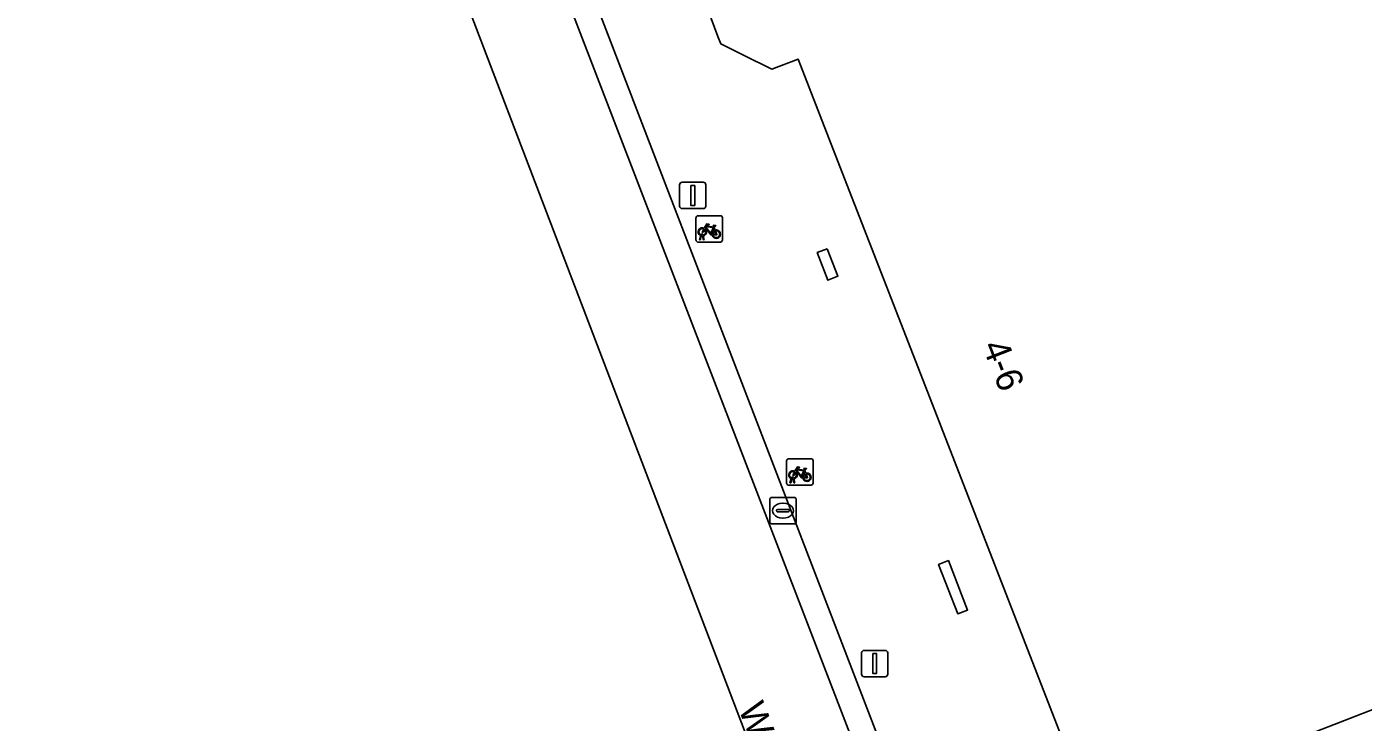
# Model space of a CAD drawing. Extents: x 160856 to 161310, y 384024 to 384878.
# Drawn here: x 160875.2 to 160925.8, y 384720.3 to 384746.6 of the extents above; entities that cross this region are included whole.
import ezdxf

# ---------------------------------------------------------------- set-up
doc = ezdxf.new("R2010")
doc.units = 0
for name, color, linetype in [('IMGEO_Fietsenrek', 7, 'Continuous'), ('IMGEO_Fietspad_gesloten', 7, 'Continuous'), ('IMGEO_Fietspad_open', 7, 'Continuous'), ('IMGEO_Kolk', 7, 'Continuous'), ('IMGEO_Lichtmast', 7, 'Continuous'), ('IMGEO_Openbare_ruimte_label', 7, 'Continuous'), ('IMGEO_Pand', 7, 'Continuous'), ('IMGEO_Pand_nummerreeks', 7, 'Continuous'), ('IMGEO_Voetpad_open', 7, 'Continuous')]:
    doc.layers.add(name, color=color, linetype=linetype)

msp = doc.modelspace()

# ---------------------------------------------------------------- linework, layer by layer
at = {"layer": 'IMGEO_Fietsenrek'}
for p, q in [((160900.511, 384738.519), (160900.511, 384739.36)), ((160900.511, 384739.36), (160900.511, 384738.519)), ((160900.586, 384739.444), (160901.427, 384739.444)), ((160901.427, 384739.444), (160900.586, 384739.444)), ((160901.511, 384739.369), (160901.511, 384738.528)), ((160901.511, 384738.528), (160901.511, 384739.369)), ((160900.638, 384738.528), (160900.677, 384738.688)), ((160900.672, 384738.528), (160900.638, 384738.528)), ((160900.707, 384738.676), (160900.672, 384738.528)), ((160900.749, 384738.7), (160900.748, 384738.704)), ((160900.79, 384738.528), (160900.756, 384738.67)), ((160900.78, 384738.711), (160900.781, 384738.704)), ((160900.788, 384738.674), (160900.823, 384738.528)), ((160900.823, 384738.528), (160900.79, 384738.528)), ((160901.198, 384738.993), (160901.234, 384738.898)), ((160901.436, 384738.444), (160900.595, 384738.444)), ((160900.595, 384738.444), (160901.436, 384738.444)), ((160903.939, 384729.325), (160903.939, 384730.166)), ((160903.939, 384730.166), (160903.939, 384729.325)), ((160904.014, 384730.25), (160904.855, 384730.25)), ((160904.855, 384730.25), (160904.014, 384730.25)), ((160904.939, 384730.175), (160904.939, 384729.334)), ((160904.939, 384729.334), (160904.939, 384730.175)), ((160904.066, 384729.334), (160904.105, 384729.494)), ((160904.135, 384729.482), (160904.1, 384729.334)), ((160904.177, 384729.506), (160904.176, 384729.51)), ((160904.218, 384729.334), (160904.184, 384729.476)), ((160904.208, 384729.517), (160904.209, 384729.51)), ((160904.216, 384729.48), (160904.251, 384729.334)), ((160904.626, 384729.799), (160904.662, 384729.704)), ((160904.864, 384729.25), (160904.023, 384729.25)), ((160904.023, 384729.25), (160904.864, 384729.25)), ((160904.1, 384729.334), (160904.066, 384729.334)), ((160904.251, 384729.334), (160904.218, 384729.334))]:
    msp.add_line(p, q, dxfattribs=at)
for points in [[(160900.824, 384738.97), (160900.919, 384739.134), (160901.005, 384739.12), (160901.007, 384739.111), (160900.951, 384739.1), (160900.924, 384739.055), (160901.18, 384739.014)], [(160901.167, 384738.989), (160900.91, 384739.03), (160900.893, 384739.001), (160901.06, 384738.781), (160901.167, 384738.989)], [(160901.18, 384739.014), (160901.205, 384739.063), (160901.199, 384739.067), (160901.176, 384739.071), (160901.164, 384739.078), (160901.163, 384739.081), (160901.165, 384739.086), (160901.26, 384739.071), (160901.262, 384739.061), (160901.252, 384739.048), (160901.24, 384739.042), (160901.226, 384739.048), (160901.198, 384738.993)], [(160900.845, 384738.918), (160900.793, 384738.828), (160900.753, 384738.803), (160900.754, 384738.85), (160900.809, 384738.944)], [(160901.12, 384738.726), (160901.07, 384738.726), (160900.879, 384738.977), (160900.86, 384738.945)], [(160901.215, 384738.891), (160901.185, 384738.968), (160901.076, 384738.75), (160901.119, 384738.75)], [(160901.149, 384738.75), (160901.269, 384738.749), (160901.225, 384738.863)], [(160901.245, 384738.87), (160901.3, 384738.725), (160901.15, 384738.725)], [(160904.252, 384729.776), (160904.347, 384729.94), (160904.433, 384729.926), (160904.435, 384729.917), (160904.379, 384729.906), (160904.352, 384729.861), (160904.608, 384729.82)], [(160904.273, 384729.724), (160904.221, 384729.634), (160904.181, 384729.609), (160904.182, 384729.656), (160904.237, 384729.75)], [(160904.548, 384729.532), (160904.498, 384729.532), (160904.307, 384729.783), (160904.288, 384729.751)], [(160904.595, 384729.795), (160904.338, 384729.836), (160904.321, 384729.807), (160904.488, 384729.587), (160904.595, 384729.795)], [(160904.643, 384729.697), (160904.613, 384729.774), (160904.504, 384729.556), (160904.547, 384729.556)], [(160904.577, 384729.556), (160904.697, 384729.555), (160904.653, 384729.669)], [(160904.673, 384729.676), (160904.728, 384729.531), (160904.578, 384729.531)], [(160904.608, 384729.82), (160904.633, 384729.869), (160904.627, 384729.873), (160904.604, 384729.877), (160904.592, 384729.884), (160904.591, 384729.887), (160904.593, 384729.892), (160904.688, 384729.877), (160904.69, 384729.867), (160904.68, 384729.854), (160904.668, 384729.848), (160904.654, 384729.854), (160904.626, 384729.799)]]:
    msp.add_lwpolyline(points, dxfattribs=at)
for centre, radius, start, end in [((160900.589, 384739.366), 0.0779, 92.4484, 184.2845), ((160900.589, 384739.366), 0.0779, 92.4484, 184.2845), ((160901.433, 384739.366), 0.0779, 2.4484, 94.2845), ((160901.433, 384739.366), 0.0779, 2.4484, 94.2845), ((160900.589, 384738.522), 0.0779, 182.4484, 274.2845), ((160900.589, 384738.522), 0.0779, 182.4484, 274.2845), ((160900.751, 384738.829), 0.159, 62.6766, 242.1369), ((160900.751, 384738.829), 0.129, 63.3192, 238.903), ((160900.731, 384738.7), 0.0499, 12.8025, 158.6934), ((160900.751, 384738.829), 0.159, 253.9967, 271.7867), ((160900.731, 384738.7), 0.0174, 12.8025, 163.4502), ((160900.751, 384738.829), 0.129, 253.415, 269.0204), ((160900.751, 384738.829), 0.129, 283.6043, 43.4302), ((160900.751, 384738.829), 0.159, 283.5766, 46.6042), ((160901.278, 384738.745), 0.159, 113.3408, 178.3217), ((160901.278, 384738.745), 0.159, 187.0065, 105.7708), ((160901.278, 384738.745), 0.129, 113.923, 177.9556), ((160901.278, 384738.745), 0.129, 188.6715, 104.5883), ((160901.433, 384738.522), 0.0779, 272.4484, 4.2845), ((160901.433, 384738.522), 0.0779, 272.4484, 4.2845), ((160904.017, 384730.172), 0.0779, 92.4484, 184.2845), ((160904.017, 384730.172), 0.0779, 92.4484, 184.2845), ((160904.861, 384730.172), 0.0779, 2.4484, 94.2845), ((160904.861, 384730.172), 0.0779, 2.4484, 94.2845), ((160904.179, 384729.635), 0.159, 62.6766, 242.1369), ((160904.179, 384729.635), 0.129, 63.3192, 238.903), ((160904.159, 384729.506), 0.0499, 12.8025, 158.6934), ((160904.179, 384729.635), 0.159, 253.9967, 271.7867), ((160904.159, 384729.506), 0.0174, 12.8025, 163.4502), ((160904.179, 384729.635), 0.129, 253.415, 269.0204), ((160904.179, 384729.635), 0.129, 283.6043, 43.4302), ((160904.179, 384729.635), 0.159, 283.5766, 46.6042), ((160904.706, 384729.551), 0.159, 113.3408, 178.3217), ((160904.706, 384729.551), 0.159, 187.0065, 105.7708), ((160904.706, 384729.551), 0.129, 113.923, 177.9556), ((160904.706, 384729.551), 0.129, 188.6715, 104.5883), ((160904.017, 384729.328), 0.0779, 182.4484, 274.2845), ((160904.017, 384729.328), 0.0779, 182.4484, 274.2845), ((160904.861, 384729.328), 0.0779, 272.4484, 4.2845), ((160904.861, 384729.328), 0.0779, 272.4484, 4.2845)]:
    msp.add_arc(centre, radius, start, end, dxfattribs=at)
at = {"layer": 'IMGEO_Fietspad_gesloten'}
msp.add_lwpolyline([(160952.428, 384599.868), (160937.604, 384638.593), (160892.484, 384755.839), (160890.883, 384755.238), (160892.527, 384749.494), (160889.824, 384754.841), (160889.132, 384754.582), (160951.015, 384592.51), (160969.346, 384573.161), (160977.866, 384562.895)], dxfattribs=at)
at = {"layer": 'IMGEO_Fietspad_open'}
msp.add_lwpolyline([(160921.747, 384682.423), (160893.385, 384756.183), (160892.484, 384755.839), (160937.604, 384638.593), (160952.428, 384599.868)], dxfattribs=at)
at = {"layer": 'IMGEO_Kolk'}
for p, q in [((160903.301, 384727.86), (160903.301, 384728.712)), ((160903.376, 384728.786), (160904.228, 384728.786)), ((160903.789, 384728.566), (160903.814, 384728.566)), ((160904.302, 384728.712), (160904.302, 384727.86)), ((160903.56, 384728.28), (160903.56, 384728.292)), ((160903.998, 384728.243), (160903.6, 384728.243)), ((160903.603, 384728.329), (160904.001, 384728.329)), ((160903.812, 384728.006), (160903.787, 384728.006)), ((160904.044, 384728.292), (160904.044, 384728.28)), ((160904.228, 384727.786), (160903.376, 384727.786))]:
    msp.add_line(p, q, dxfattribs=at)
for points in [[(160903.301, 384727.86), (160903.301, 384728.712)], [(160903.376, 384728.786), (160904.228, 384728.786)], [(160904.302, 384728.712), (160904.302, 384727.86)], [(160904.228, 384727.786), (160903.376, 384727.786)]]:
    msp.add_lwpolyline(points, dxfattribs=at)
for centre, radius, start, end in [((160903.378, 384728.71), 0.0765, 91.552, 178.448), ((160903.378, 384728.71), 0.0765, 91.552, 178.448), ((160904.226, 384728.71), 0.0765, 1.552, 88.448), ((160904.226, 384728.71), 0.0765, 1.552, 88.448), ((160903.6, 384728.289), 0.0403, 85.8775, 175.7526), ((160903.597, 384728.279), 0.0366, 178.938, 274.7102), ((160904.001, 384728.286), 0.043, 264.8664, 352.4533), ((160904.005, 384728.291), 0.0386, 1.7309, 96.639), ((160903.378, 384727.862), 0.0765, 181.552, 268.448), ((160903.378, 384727.862), 0.0765, 181.552, 268.448), ((160904.226, 384727.862), 0.0765, 271.552, 358.448), ((160904.226, 384727.862), 0.0765, 271.552, 358.448)]:
    msp.add_arc(centre, radius, start, end, dxfattribs=at)
for centre, major_axis, ratio, start_param, end_param in [((160903.788, 384728.286), (-0.387, 0.002), 0.722429, 4.712389, 7.853982), ((160903.813, 384728.286), (-0.39, 0.002), 0.717154, 1.570796, 4.712389)]:
    msp.add_ellipse(centre, major_axis=major_axis, ratio=ratio, start_param=start_param, end_param=end_param, dxfattribs=at)
at = {"layer": 'IMGEO_Lichtmast'}
for p, q in [((160899.891, 384739.811), (160899.891, 384740.611)), ((160899.891, 384740.611), (160899.891, 384739.811)), ((160899.991, 384740.711), (160900.781, 384740.711)), ((160900.781, 384740.711), (160899.991, 384740.711)), ((160900.881, 384740.611), (160900.881, 384739.811)), ((160900.881, 384739.811), (160900.881, 384740.611)), ((160900.781, 384739.711), (160899.991, 384739.711)), ((160899.991, 384739.711), (160900.781, 384739.711)), ((160906.776, 384722.101), (160906.776, 384722.901)), ((160906.776, 384722.901), (160906.776, 384722.101)), ((160906.876, 384723.001), (160907.666, 384723.001)), ((160907.666, 384723.001), (160906.876, 384723.001)), ((160907.766, 384722.901), (160907.766, 384722.101)), ((160907.766, 384722.101), (160907.766, 384722.901)), ((160907.666, 384722.001), (160906.876, 384722.001)), ((160906.876, 384722.001), (160907.666, 384722.001))]:
    msp.add_line(p, q, dxfattribs=at)
for points in [[(160900.311, 384740.586), (160900.461, 384740.586), (160900.461, 384739.836), (160900.311, 384739.836), (160900.311, 384740.586)], [(160907.196, 384722.876), (160907.346, 384722.876), (160907.346, 384722.126), (160907.196, 384722.126), (160907.196, 384722.876)]]:
    msp.add_lwpolyline(points, dxfattribs=at)
for centre, start, end in [((160899.991, 384740.611), 90, 180), ((160899.991, 384740.611), 90, 180), ((160900.781, 384740.611), 0, 90), ((160900.781, 384740.611), 360, 90), ((160899.991, 384739.811), 180, 270), ((160899.991, 384739.811), 180, 270), ((160900.781, 384739.811), 270, 0), ((160900.781, 384739.811), 270, 0), ((160906.876, 384722.901), 90, 180), ((160906.876, 384722.901), 90, 180), ((160907.666, 384722.901), 0, 90), ((160907.666, 384722.901), 360, 90), ((160906.876, 384722.101), 180, 270), ((160906.876, 384722.101), 180, 270), ((160907.666, 384722.101), 270, 0), ((160907.666, 384722.101), 270, 0)]:
    msp.add_arc(centre, 0.1, start, end, dxfattribs=at)
at = {"layer": 'IMGEO_Pand'}
for points in [[(160949.481, 384748.048), (160945.396, 384764.217), (160943.796, 384763.605), (160943.769, 384763.705), (160933.141, 384759.554), (160917.89, 384753.764), (160914.236, 384752.377), (160912.501, 384751.718), (160912.447, 384751.855), (160900.915, 384747.341), (160901.332, 384746.227), (160901.445, 384745.94), (160902.333, 384745.503), (160903.382, 384744.987), (160904.378, 384745.364), (160905.955, 384741.304), (160909.277, 384732.755), (160914.414, 384719.534), (160912.528, 384718.769), (160913.025, 384717.51), (160913.036, 384716.255), (160913.229, 384715.759), (160953.769, 384731.511)], [(160905.477, 384738.194), (160905.097, 384738.047), (160905.502, 384737.004), (160905.882, 384737.152)], [(160956.01, 384714.035), (160954.963, 384716.711), (160957.385, 384717.71), (160954.094, 384731.251), (160953.852, 384731.189), (160953.769, 384731.511), (160913.229, 384715.759), (160919.422, 384699.819)], [(160910.058, 384726.397), (160909.687, 384726.253), (160910.414, 384724.383), (160910.785, 384724.527)]]:
    msp.add_lwpolyline(points, close=True, dxfattribs=at)
at = {"layer": 'IMGEO_Voetpad_open'}
msp.add_lwpolyline([(160875.191, 384805.653), (160887.436, 384774.8), (160893.385, 384756.183), (160921.747, 384682.423), (160925.586, 384683.954), (160923.413, 384689.547), (160919.502, 384699.614), (160919.422, 384699.819), (160913.229, 384715.759), (160913.036, 384716.255), (160913.025, 384717.51), (160912.528, 384718.769), (160914.414, 384719.534), (160909.277, 384732.755), (160905.955, 384741.304), (160904.378, 384745.364), (160903.382, 384744.987), (160902.333, 384745.503), (160901.445, 384745.94), (160901.332, 384746.227), (160900.915, 384747.341)], dxfattribs=at)
for points in [[(160905.477, 384738.194), (160905.882, 384737.152), (160905.502, 384737.004), (160905.097, 384738.047)], [(160909.687, 384726.253), (160910.058, 384726.397), (160910.785, 384724.527), (160910.414, 384724.383)]]:
    msp.add_lwpolyline(points, close=True, dxfattribs=at)

# ---------------------------------------------------------------- texts
at = {"layer": 'IMGEO_Openbare_ruimte_label'}
msp.add_text('Woenselse Markt', height=1, rotation=291.0457, dxfattribs=at).set_placement((160902.104, 384720.805))
at = {"layer": 'IMGEO_Pand_nummerreeks'}
msp.add_text('4-6', height=1, rotation=291.3826, dxfattribs=at).set_placement((160911.328, 384734.516))

doc.saveas('drawing.dxf')
